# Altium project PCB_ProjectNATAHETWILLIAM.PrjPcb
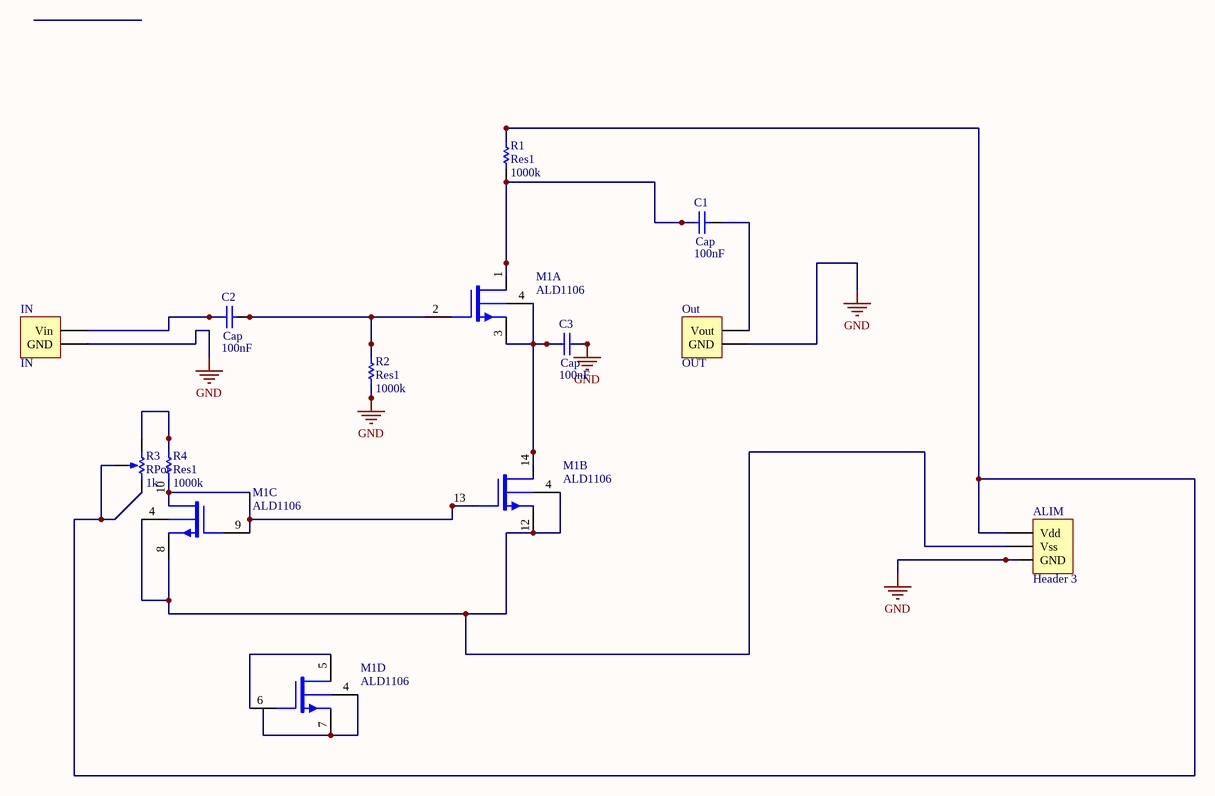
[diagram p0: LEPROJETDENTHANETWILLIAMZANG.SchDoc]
1 sheet, 11 parts. Net scope: global (net labels, ports and power ports of the same name join across sheets).
Board file: PCB3.PcbDoc

## Sheet LEPROJETDENTHANETWILLIAMZANG.SchDoc
size A4

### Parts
ALIM  Header 3  [HDR1X3]
C1  Cap  value 100nF  [RAD-0.3]
C2  Cap  value 100nF  [RAD-0.3]
C3  Cap  value 100nF  [RAD-0.3]
IN  IN  [HDR1X2]
M1  ALD1106  [DIP-14]  (parts A,B,C,D of 4)
Out  OUT  [HDR1X2]
R1  Res1  value 1000k  [AXIAL-0.3]
R2  Res1  value 1000k  [AXIAL-0.3]
R3  RPot  value 1k  [VR5]
R4  Res1  value 1000k  [AXIAL-0.3]

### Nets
GND: ALIM.3(GND) C3.2 IN.1(GND) Out.1(GND) R2.1
NetALIM_1: ALIM.1(Vdd) R1.2 R3.2(TAP) R3.3(BOT)
NetALIM_2: ALIM.2(Vss) M1.4(V-) M1.8(SN3) M1.12(SN2)
NetC1_1: C1.1 M1.1(DN1) R1.1
NetC1_2: C1.2 Out.2(Vout)
NetC2_1: C2.1 IN.2(Vin)
NetC2_2: C2.2 M1.2(GN1) R2.2
NetC3_1: C3.1 M1.3(SN1) M1.4(V-) M1.14(DN2)
NetM1_4: M1.4(V-) M1.7(SN4)
NetM1_5: M1.5(DN4) M1.6(GN4)
NetM1_9: M1.9(GN3) M1.10(DN3) M1.13(GN2) R4.1
NetR3_1: R3.1(TOP) R4.2

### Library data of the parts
ALIM = Header 3: Header, 3-Pin
C1-C3 = Cap: Capacitor
IN Out = Header 2: Header, 2-Pin
M1 = ALD1106: Quad N-channel matched MOSFET array
R1 R2 R4 = Res1: Resistor
R3 = RPot: Potentiometer; Sim Note: Enter the Resistance value and the set point into parameter fields.; Set Position: 0.5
